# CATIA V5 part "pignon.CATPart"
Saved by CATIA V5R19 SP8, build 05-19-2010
Part number: PignonG
Publications: "Axe", "Appui_1", "Appui_2"
Bounding box of the stored display mesh (mm): x 0 to 87.5, y -30.34 to 30.34, z -30.337 to 30.337
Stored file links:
  G:\EU_thinkMotion\CFAO_2010\MMS_groupe2\MMS_groupe2\OK\melguidj\cfao_elguidj_2AMMSgrB\Modèle 3D\pignon.CATPart
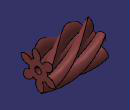
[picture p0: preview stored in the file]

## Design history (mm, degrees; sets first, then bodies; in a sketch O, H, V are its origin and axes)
Parameters
  diametre_primitif = 48.4974 mm {= module_app *z_dent}
  diametre_tete = 62.4974 mm {= diametre_primitif +2*module_normal}
  diametre_pied = 30.9974 mm {= diametre_primitif -2*1.25*module_normal}
  diametre_base = 42 mm {= diametre_primitif *cos(angle_pression )}
  module_normal = 7 mm
  module_app = 8.0829 mm {= module_normal /cos(angle_helice )}
  angle_pression = 30 deg
  angle_helice = 30 deg
  z_dent = 6
  diametre_alesage = -11.0026 mm {= diametre_pied -6*module_normal}
  largeur_denture = 87.5 mm
  pas_helice = 263.8938 mm {= PI *diametre_primitif /tan(angle_helice )}
Set1
  Point1: (0, 0, 0)
  Line1: type PtDir, RefPoint Point1, Direction yz-plane, Start 0, End 20
  Point2: (-5, 0, 24.2487 {= diametre_primitif /2})
  Helix1: Direction Line1, RefPoint Point2, Pitch 263.8938 {= pas_helice}, Height 97.5 {= largeur_denture +10mm}, TaperAngle 0
  Line2: type PtDir, RefPoint Point1, Direction xy-plane, Start 0, End 20
  Plane1: type Normal, Curve Helix1, RefPoint Point2
Body1 (main body)
  Sketch1 on yz-plane, origin (0, 0, 0), H (0, 1, 0), V (0, 0, 1)
    circle A1 centre (0, 0) radius 15
    circle A2 centre (0, 0) radius 5.5013
    radius A2 = -5.5013 {= diametre_alesage /2}
    radius A1 = 15
  Pad1: profile Sketch1, direction (1, 0, 0), length 87.5 {= largeur_denture}
  Sketch2 on Plane1, origin (-6.8068, 3.1295, 0), H (-0.5, 0.866, 0), V (0, 0, 1)
    construction circle A1 centre (-3.6136, 0) radius 24.2487
    reference intersected point E1 (-3.6136, 0) from axis of face of Pad1
    reference projected point E2 (-3.6136, 24.2487) from Point2
    construction circle A2 centre (-3.6136, 0) radius 21
    construction line L1 (-3.6136, 24.2487) -> (-3.6136, 0)
    point P2 (-3.6136, 24.2487)
    construction line L2 (-3.6136, 0) -> (-14.1136, 18.1865)
    point P3 (-14.1136, 18.1865)
    arc A3 centre (-14.1136, 18.1865) radius 12.1244 from (-5.778, 9.3821) to (-10.4773, 29.7527) ccw
    point P4 (-3.6136, 24.2487)
    construction line L3 (-3.6136, 0) -> (-9.0644, 23.6281)
    point P5 (-3.6136, 0)
    point P6 (-9.0644, 23.6281)
    arc A4 centre (-2.1417, 20.9484) radius 12.1244 from (-5.778, 9.3821) to (-10.4773, 29.7527) cw
    radius A2 = 21 {= diametre_base /2}
    angle L2 L1 = 30 {= angle_pression}
    angle L3 L1 = 12.9904 {= PI *module_normal /4/(diametre_primitif /2)*1rad}
    concentricity: E1 A1
    coincidence: A1 E2, P2 A1, P3 A2, A3 P4, P4 L1, A3 P2, P5 H, P5 L2, P6 A1
    vertical: L1 V
    symmetry: A4 A3 L3
  Rib1: profile Sketch2, centre curve Helix1
  CircPattern1: of Rib1, instances 6 {= z_dent}, angular step 60 {= 360.0*1 deg/CircPattern1.AngularNumber}, axis from face
  Split1: SplitPlane face
  Split2: SplitPlane face
  Sketch3 on yz-plane, origin (0, 0, 0), H (0, 1, 0), V (0, 0, 1)
    circle A1 centre (0, 0) radius 31.5
    radius A1 = 31.5
  Pocket1: profile Sketch3, direction (1, 0, 0), through (limit type 6), outer side, deactivated
  Sketch4 on yz-plane, origin (0, 0, 0), H (0, 1, 0), V (0, 0, 1)
    circle A1 centre (0, 0) radius 0.6896
    radius A1 = 1.4987 {= diametre_pied/2 -2*module_normal}
  Pocket2: profile Sketch4, direction (1, 0, 0), through (limit type 6), deactivated
  Sketch5 on face of Split2, origin (87.5, 0, 0), H (0, 1, 0), V (0, 0, 1)
    circle A1 centre (0, 0) radius 24.2487
    radius A1 = 24.2487 {= diametre_primitif /2}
